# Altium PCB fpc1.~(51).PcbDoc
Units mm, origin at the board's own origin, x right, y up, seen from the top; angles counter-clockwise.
Board outline 89.5 x 7.33 mm, 2 copper layers (Top Layer, Bottom Layer), stack 0.049 mm thick; 5 components, 5 nets, 20 pads, 6 vias.
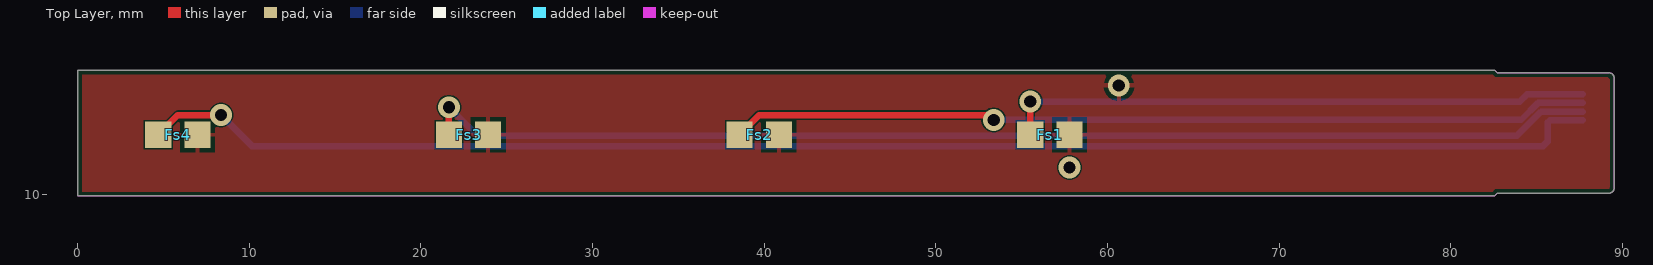
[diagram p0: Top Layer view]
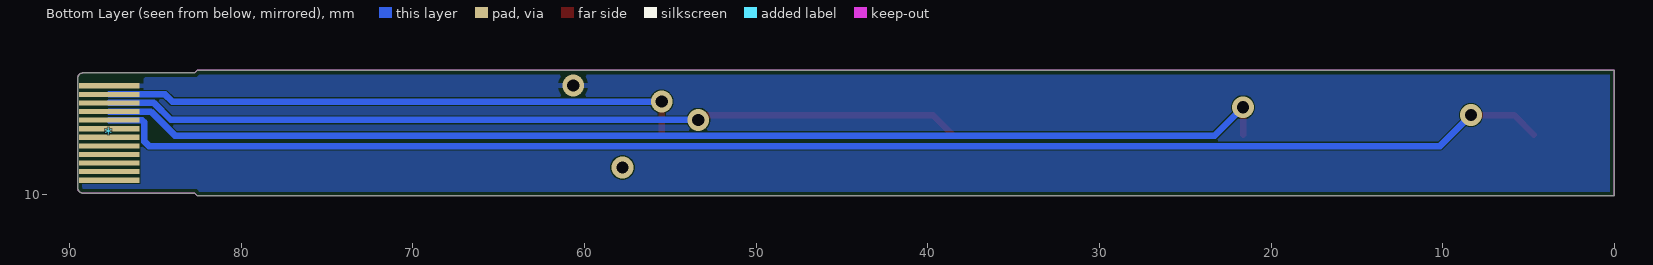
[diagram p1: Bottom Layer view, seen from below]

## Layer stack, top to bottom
Top Solder: solder mask 0.0102, Solder Resist, Dk 3.5
Top Layer: signal copper 0.012
Dielectric 1: dielectric 0.025, FR-4, Dk 4.8
Bottom Layer: signal copper 0.012
Bottom Solder: solder mask 0.0102, Solder Resist, Dk 3.5

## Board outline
0.013,9.893 0.013,17.225 82.547,17.225 82.713,17.059 89.213,17.059 cw(c89.213,16.759) 89.513,16.759 89.513,10.359 cw(c89.213,10.359) 89.213,10.059 82.713,10.059 82.547,9.893

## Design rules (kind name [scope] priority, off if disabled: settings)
BoardOutlineClearance [All] p1: gap=0 ignorepadtopadclearanceinfootprint=FALSE except(0.254: Via-OutlineEdge Via-CavityEdge Via-CutoutEdge Via-SplitBarrior Fill-OutlineEdge Fill-CavityEdge Fill-CutoutEdge Fill-SplitBarrior Poly-OutlineEdge Poly-CavityEdge Poly-CutoutEdge Poly-SplitBarrior Region-OutlineEdge Region-CavityEdge Region-CutoutEdge Region-SplitBarrior Text-OutlineEdge Text-CavityEdge Text-CutoutEdge Text-SplitBarrior)
Clearance [All] p1: gap=0.076 ignorepadtopadclearanceinfootprint=TRUE except(0: Arc-Hole Track-Hole SMDPad-Hole THPad-Hole Via-Hole Fill-Hole Poly-Hole Region-Hole Text-Hole)
DiffPairsRouting [All] p1: maxlimit=0.254 minlimit=0.254 mostfreqgap=0.254 toplayer_minwidth=0.381 toplayer_maxwidth=0.381 toplayer_prefwidth=0.381 bottomlayer_minwidth=0.381 bottomlayer_maxwidth=0.381 bottomlayer_prefwidth=0.381 substack1={6BAC4FC8-8DE6-4E41-AF8A-9441F3E19743} toplayer_{6bac4fc8-8de6-4e41-af8a-9441f3e19743}_minwidth=0.381 toplayer_{6bac4fc8-8de6-4e41-af8a-9441f3e19743}_maxwidth=0.381 toplayer_{6bac4fc8-8de6-4e41-af8a-9441f3e19743}_prefwidth=0.381 bottomlayer_{6bac4fc8-8de6-4e41-af8a-9441f3e19743}_minwidth=0.381 bottomlayer_{6bac4fc8-8de6-4e41-af8a-9441f3e19743}_maxwidth=0.381 bottomlayer_{6bac4fc8-8de6-4e41-af8a-9441f3e19743}_prefwidth=0.381 maxuncoupledlength=12.7
MinimumSolderMaskSliver [All] p1: minsoldermaskwidth=0.05
PlaneConnect [All] p1: planeconnectstyle=Direct reliefexpansion=0.508 reliefentries=4 reliefconductorwidth=0.254 reliefairgap=0.254
PolygonConnect [All] p1: connectstyle=Relief reliefconductorwidth=0.254 reliefentries=4 polygonreliefangle="90 Angle" airgapwidth=0.254
RoutingVias [All] p1: holewidth=0.711 width=1.27 viastyle="Through Hole" minholewidth=0.711 minwidth=1.27 maxholewidth=0.711 maxwidth=1.27
SilkToSilkClearance [All] p1: silktosilkclearance=0.05
SilkToSolderMaskClearance [IsPad] p1: minsilkscreentomaskgap=0.05 clearancetoexposedcopper=TRUE
SolderMaskExpansion [All] p1: expansion=0.102 istentingtop=FALSE
Width [All] p1: maxlimit=0.508 minlimit=0.127 preferedwidth=0.381 substack1={6BAC4FC8-8DE6-4E41-AF8A-9441F3E19743} toplayer_{6bac4fc8-8de6-4e41-af8a-9441f3e19743}_minwidth=0.254 toplayer_{6bac4fc8-8de6-4e41-af8a-9441f3e19743}_maxwidth=0.254 toplayer_{6bac4fc8-8de6-4e41-af8a-9441f3e19743}_prefwidth=0.254 bottomlayer_{6bac4fc8-8de6-4e41-af8a-9441f3e19743}_minwidth=0.254 bottomlayer_{6bac4fc8-8de6-4e41-af8a-9441f3e19743}_maxwidth=0.254 bottomlayer_{6bac4fc8-8de6-4e41-af8a-9441f3e19743}_prefwidth=0.254 minimp=50.000000 maximp=50.000000 favimp=50.000000
25 further rules are at their usual default settings.

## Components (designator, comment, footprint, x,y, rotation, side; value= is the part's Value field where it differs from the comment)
* "FPC_connector" FPC_connector 87.677,13.559 r180 bottom
Fs1 "ForceSensor" sensor_connector 56.642,13.462 r0 top
Fs2 "ForceSensor" sensor_connector 39.709,13.462 r0 top
Fs3 "ForceSensor" sensor_connector 22.775,13.462 r0 top
Fs4 "ForceSensor" sensor_connector 5.842,13.462 r0 top

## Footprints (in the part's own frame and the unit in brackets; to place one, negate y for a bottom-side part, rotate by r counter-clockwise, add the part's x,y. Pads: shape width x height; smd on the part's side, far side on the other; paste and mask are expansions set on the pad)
FPC_connector [mm]
  rect 3.5x0.3 smd: 0(0,2.75) 1(0,2.25) 2(0,1.75) 3(0,1.25) 4(0,0.75) 5(0,0.25) 6(0,-0.25) 7(0,-0.75) 8(0,-1.25) 9(0,-1.75) 10(0,-2.25) 11(0,-2.75)
sensor_connector [mil]
  rect 60x60 smd: 0(-45,0) 1(45,0)

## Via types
v1: diameter 1.27, hole 0.711, Top Layer to Bottom Layer, 6 vias

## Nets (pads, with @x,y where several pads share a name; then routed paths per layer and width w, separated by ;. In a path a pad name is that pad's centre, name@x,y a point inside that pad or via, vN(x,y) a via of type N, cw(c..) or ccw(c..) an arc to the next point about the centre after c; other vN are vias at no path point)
FS1: *.1 Fs1.0 | length 34.3
  Top Layer w0.381: Fs1.0 v1(55.499,15.392)
  Bottom Layer w0.381: v1(55.499,15.392) 84.013,15.392 84.43,15.809 *.1
FS2: *.2 Fs2.0 | length 50.1
  Top Layer w0.381: Fs2.0 39.709,14.605 53.086,14.605 v1(53.365,14.326)
  Bottom Layer w0.381: v1(53.365,14.326) 84.094,14.326 85.077,15.309 *.2
FS3: *.3 Fs3.0 | length 68.9
  Top Layer w0.381: Fs3.0 v1(21.632,15.062)
  Bottom Layer w0.381: v1(21.632,15.062) 23.283,13.411 83.854,13.411 85.252,14.809 *.3
FS4: *.4 Fs4.0 | length 85.5
  Top Layer w0.381: Fs4.0 5.842,14.605 v1(8.357,14.605)
  Bottom Layer w0.381: v1(8.357,14.605) 10.16,12.802 85.369,12.802 85.632,13.064 85.632,14.174 85.767,14.309 *.4
GND: *.0 Fs1.1 Fs2.1 Fs3.1 Fs4.1
  other v1: 60.655,16.332
pads on no net: *.5 *.6 *.7 *.8 *.9 *.10 *.11
copper on no net:
  other v1: 57.785,11.557

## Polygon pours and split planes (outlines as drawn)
GND on Top Layer "GND_L01_P002" (solid, pour order 2): 1.016,21.209 0,20.193 0,6.985 89.535,6.985 92.456,9.906 92.202,10.16 92.202,18.161
GND on Bottom Layer "GND_L02_P003" (solid, pour order 3): 0.127,18.669 0.127,8.89 1.778,7.239 92.583,7.239 92.583,18.923 91.567,19.939

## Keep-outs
Keep-Out Layer:
  the board outline again, w0.013

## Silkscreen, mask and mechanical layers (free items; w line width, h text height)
Board Shape:
  the board outline again, w0.013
